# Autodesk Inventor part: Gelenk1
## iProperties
Created: 2005-01
Part Number: Gelenk1
Document SubType Name: Modeling
Designer: Administrator
Manufacturer: Standard
Standards Organization: Custom
Material: Stainless Steel, 440C
Author: Administrator
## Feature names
1. Extrusion1
2. Extrusion2
3. Extrusion3
4. Extrusion4
5. Hole1
6. Hole2
7. Fillet1
8. Fillet2
9. Fillet3
10. Fillet4
11. Fillet9
12. Fillet10
13. Fillet11
14. Fillet13
15. Fillet14
